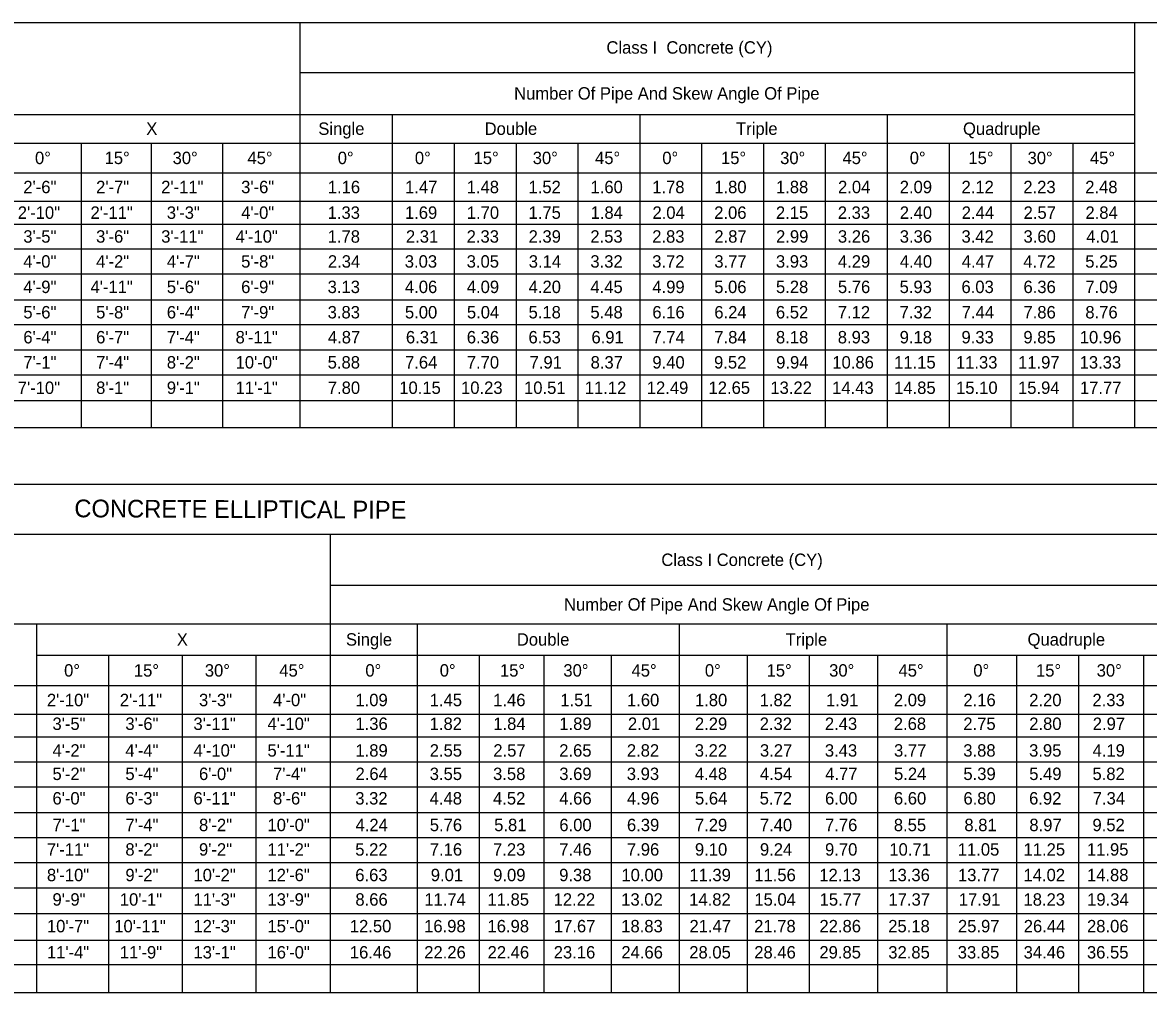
# Model space of a CAD drawing. Extents: x 10029 to 10796, y 10063 to 10519.
# Drawn here: x 10299.4 to 10616.8, y 10063.2 to 10336.7 of the extents above; entities that cross this region are included whole.
import ezdxf

# ---------------------------------------------------------------- set-up
doc = ezdxf.new("R2010")
doc.units = 0
doc.layers.add('Default', color=7, linetype='Continuous')
doc.layers.add('Dimension', color=7, linetype='Continuous')

msp = doc.modelspace()

# ---------------------------------------------------------------- linework, layer by layer
at = {"layer": 'Default'}
for p, q in [((10039.72, 10336.74), (10681.45, 10336.74)), ((10377.67, 10222.58), (10377.67, 10336.74)), ((10612.98, 10222.58), (10612.98, 10336.74)), ((10377.67, 10322.67), (10612.98, 10322.67)), ((10079.67, 10310.85), (10612.98, 10310.85)), ((10403.72, 10222.58), (10403.72, 10310.85)), ((10473.47, 10222.58), (10473.47, 10310.85)), ((10543.23, 10222.58), (10543.23, 10310.85)), ((10294.71, 10302.76), (10612.98, 10302.76)), ((10315.99, 10222.58), (10315.99, 10302.76)), ((10335.73, 10222.58), (10335.73, 10302.76)), ((10355.84, 10222.58), (10355.84, 10302.76)), ((10421.16, 10222.58), (10421.16, 10302.76)), ((10438.6, 10222.58), (10438.6, 10302.76)), ((10456.04, 10222.58), (10456.04, 10302.76)), ((10490.91, 10222.58), (10490.91, 10302.76)), ((10508.35, 10222.58), (10508.35, 10302.76)), ((10525.79, 10222.58), (10525.79, 10302.76)), ((10560.67, 10222.58), (10560.67, 10302.76)), ((10578.1, 10222.58), (10578.1, 10302.76)), ((10595.54, 10222.58), (10595.54, 10302.76)), ((10039.72, 10294.39), (10681.45, 10294.39)), ((10039.72, 10286.34), (10681.45, 10286.34)), ((10039.72, 10279.92), (10681.45, 10279.92)), ((10039.72, 10272.9), (10681.45, 10272.9)), ((10039.72, 10265.84), (10681.45, 10265.84)), ((10039.72, 10258.56), (10681.45, 10258.56)), ((10039.72, 10251.55), (10681.45, 10251.55)), ((10039.72, 10244.47), (10681.45, 10244.47)), ((10039.72, 10237.36), (10681.45, 10237.36)), ((10039.72, 10230.15), (10681.45, 10230.15)), ((10039.72, 10222.58), (10681.45, 10222.58)), ((10040.76, 10206.56), (10696.75, 10206.56)), ((10040.76, 10192.44), (10696.75, 10192.44)), ((10386.23, 10063.22), (10386.23, 10192.44)), ((10386.23, 10178.05), (10632.55, 10178.05)), ((10084.96, 10167.22), (10632.55, 10167.22)), ((10303.39, 10063.22), (10303.39, 10167.22)), ((10410.73, 10063.22), (10410.73, 10167.22)), ((10484.61, 10063.22), (10484.61, 10167.22)), ((10560.04, 10063.22), (10560.04, 10167.22)), ((10303.39, 10158.32), (10632.55, 10158.32)), ((10323.73, 10063.22), (10323.73, 10158.32)), ((10344.5, 10063.22), (10344.5, 10158.32)), ((10365.25, 10063.22), (10365.25, 10158.32)), ((10428.17, 10063.22), (10428.17, 10158.32)), ((10446.47, 10063.22), (10446.47, 10158.32)), ((10465.46, 10063.22), (10465.46, 10158.32)), ((10503.77, 10063.22), (10503.77, 10158.32)), ((10521.21, 10063.22), (10521.21, 10158.32)), ((10540.54, 10063.22), (10540.54, 10158.32)), ((10579.72, 10063.22), (10579.72, 10158.32)), ((10597.16, 10063.22), (10597.16, 10158.32)), ((10615.46, 10063.22), (10615.46, 10158.32)), ((10040.76, 10149.78), (10696.75, 10149.78)), ((10040.76, 10141.72), (10696.75, 10141.72)), ((10040.76, 10135.31), (10696.75, 10135.31)), ((10040.76, 10128.29), (10696.75, 10128.29)), ((10040.76, 10121.22), (10696.75, 10121.22)), ((10040.76, 10113.95), (10696.75, 10113.95)), ((10040.76, 10106.93), (10696.75, 10106.93)), ((10040.76, 10099.86), (10696.75, 10099.86)), ((10040.76, 10092.75), (10696.75, 10092.75)), ((10040.76, 10085.54), (10696.75, 10085.54)), ((10040.76, 10077.97), (10696.75, 10077.97)), ((10040.76, 10071.08), (10696.75, 10071.08)), ((10040.76, 10063.22), (10696.75, 10063.22))]:
    msp.add_line(p, q, dxfattribs=at)

# ---------------------------------------------------------------- texts
at = {"layer": 'Dimension'}
for s, p in [('Class I  Concrete (CY)', (10463.98, 10327.96)), ('Number Of Pipe And Skew Angle Of Pipe', (10437.96, 10315.01)), ('X', (10334.25, 10305.06)), ('Single', (10382.76, 10305.06)), ('Double', (10429.64, 10305.06)), ('Triple', (10500.53, 10305.06)), ('Quadruple', (10564.51, 10305.06)), ('0°', (10302.89, 10296.82)), ('15°', (10322.51, 10296.82)), ('30°', (10341.68, 10296.82)), ('45°', (10362.78, 10296.82)), ('0°', (10388.24, 10296.82)), ('0°', (10409.98, 10296.82)), ('15°', (10426.53, 10296.82)), ('30°', (10443.21, 10296.82)), ('45°', (10460.78, 10296.82)), ('0°', (10479.74, 10296.82)), ('15°', (10496.28, 10296.82)), ('30°', (10512.96, 10296.82)), ('45°', (10530.53, 10296.82)), ('0°', (10549.49, 10296.82)), ('15°', (10566.03, 10296.82)), ('30°', (10582.71, 10296.82)), ('45°', (10600.29, 10296.82)), ('Class I Concrete (CY)', (10479.46, 10183.49)), ('Number Of Pipe And Skew Angle Of Pipe', (10452.03, 10170.89)), ('X', (10342.87, 10161.02)), ('Single', (10390.55, 10161.02)), ('Double', (10438.72, 10161.02)), ('Triple', (10514.51, 10161.02)), ('Quadruple', (10582.71, 10161.02)), ('0°', (10311.1, 10152.3)), ('15°', (10330.77, 10152.3)), ('30°', (10350.77, 10152.3)), ('45°', (10371.77, 10152.3)), ('0°', (10396.02, 10152.3)), ('0°', (10416.99, 10152.3)), ('15°', (10433.97, 10152.3)), ('30°', (10451.85, 10152.3)), ('45°', (10471.06, 10152.3)), ('0°', (10491.74, 10152.3)), ('15°', (10509.14, 10152.3)), ('30°', (10526.77, 10152.3)), ('45°', (10546.32, 10152.3)), ('0°', (10567.42, 10152.3)), ('15°', (10585.09, 10152.3)), ('30°', (10602.2, 10152.3))]:
    msp.add_text(s, height=3.5, dxfattribs=at).set_placement(p)
for s, height, rotation, p in [('2\'-6"', 3.5, 0, (10299.6, 10288.61)), ('2\'-7"', 3.5, 0, (10320.12, 10288.61)), ('2\'-11"', 3.5, 0, (10338.47, 10288.61)), ('3\'-6"', 3.5, 0, (10361.01, 10288.61)), ('1.16', 3.5, 0, (10385.43, 10288.61)), ('1.47', 3.5, 0, (10407.22, 10288.61)), ('1.48', 3.5, 0, (10424.59, 10288.61)), ('1.52', 3.5, 0, (10442.02, 10288.61)), ('1.60', 3.5, 0, (10459.5, 10288.61)), ('1.78', 3.5, 0, (10476.9, 10288.61)), ('1.80', 3.5, 0, (10494.38, 10288.61)), ('1.88', 3.5, 0, (10511.78, 10288.61)), ('2.04', 3.5, 0, (10529.28, 10288.61)), ('2.09', 3.5, 0, (10546.68, 10288.61)), ('2.12', 3.5, 0, (10564.09, 10288.61)), ('2.23', 3.5, 0, (10581.52, 10288.61)), ('2.48', 3.5, 0, (10598.97, 10288.61)), ('2\'-10"', 3.5, 0, (10298.03, 10281.38)), ('2\'-11"', 3.5, 0, (10318.55, 10281.38)), ('3\'-3"', 3.5, 0, (10340.05, 10281.38)), ('4\'-0"', 3.5, 0, (10361.01, 10281.38)), ('1.33', 3.5, 0, (10385.39, 10281.38)), ('1.69', 3.5, 0, (10407.18, 10281.38)), ('1.70', 3.5, 0, (10424.62, 10281.38)), ('1.75', 3.5, 0, (10442.03, 10281.38)), ('1.84', 3.5, 0, (10459.52, 10281.38)), ('2.04', 3.5, 0, (10476.96, 10281.38)), ('2.06', 3.5, 0, (10494.37, 10281.38)), ('2.15', 3.5, 0, (10511.78, 10281.38)), ('2.33', 3.5, 0, (10529.21, 10281.38)), ('2.40', 3.5, 0, (10546.69, 10281.38)), ('2.44', 3.5, 0, (10564.15, 10281.38)), ('2.57', 3.5, 0, (10581.6, 10281.38)), ('2.84', 3.5, 0, (10599.03, 10281.38)), ('3\'-5"', 3.5, 0, (10299.6, 10274.66)), ('3\'-6"', 3.5, 0, (10320.12, 10274.66)), ('3\'-11"', 3.5, 0, (10338.47, 10274.66)), ('4\'-10"', 3.5, 0, (10359.44, 10274.66)), ('1.78', 3.5, 0, (10385.4, 10274.66)), ('2.31', 3.5, 0, (10407.46, 10274.66)), ('2.33', 3.5, 0, (10424.58, 10274.66)), ('2.39', 3.5, 0, (10442.05, 10274.66)), ('2.53', 3.5, 0, (10459.45, 10274.66)), ('2.83', 3.5, 0, (10476.89, 10274.66)), ('2.87', 3.5, 0, (10494.41, 10274.66)), ('2.99', 3.5, 0, (10511.81, 10274.66)), ('3.26', 3.5, 0, (10529.25, 10274.66)), ('3.36', 3.5, 0, (10546.68, 10274.66)), ('3.42', 3.5, 0, (10564.09, 10274.66)), ('3.60', 3.5, 0, (10581.57, 10274.66)), ('4.01', 3.5, 0, (10599.28, 10274.66)), ('4\'-0"', 3.5, 0, (10299.6, 10267.62)), ('4\'-2"', 3.5, 0, (10320.12, 10267.62)), ('4\'-7"', 3.5, 0, (10340.05, 10267.62)), ('5\'-8"', 3.5, 0, (10361.01, 10267.62)), ('2.34', 3.5, 0, (10385.46, 10267.62)), ('3.03', 3.5, 0, (10407.14, 10267.62)), ('3.05', 3.5, 0, (10424.59, 10267.62)), ('3.14', 3.5, 0, (10442.09, 10267.62)), ('3.32', 3.5, 0, (10459.46, 10267.62)), ('3.72', 3.5, 0, (10476.89, 10267.62)), ('3.77', 3.5, 0, (10494.41, 10267.62)), ('3.93', 3.5, 0, (10511.77, 10267.62)), ('4.29', 3.5, 0, (10529.25, 10267.62)), ('4.40', 3.5, 0, (10546.69, 10267.62)), ('4.47', 3.5, 0, (10564.16, 10267.62)), ('4.72', 3.5, 0, (10581.52, 10267.62)), ('5.25', 3.5, 0, (10598.98, 10267.62)), ('4\'-9"', 3.5, 0, (10299.6, 10260.45)), ('4\'-11"', 3.5, 0, (10318.55, 10260.45)), ('5\'-6"', 3.5, 0, (10340.05, 10260.45)), ('6\'-9"', 3.5, 0, (10361.01, 10260.45)), ('3.13', 3.5, 0, (10385.39, 10260.45)), ('4.06', 3.5, 0, (10407.18, 10260.45)), ('4.09', 3.5, 0, (10424.62, 10260.45)), ('4.20', 3.5, 0, (10442.06, 10260.45)), ('4.45', 3.5, 0, (10459.47, 10260.45)), ('4.99', 3.5, 0, (10476.93, 10260.45)), ('5.06', 3.5, 0, (10494.37, 10260.45)), ('5.28', 3.5, 0, (10511.78, 10260.45)), ('5.76', 3.5, 0, (10529.25, 10260.45)), ('5.93', 3.5, 0, (10546.64, 10260.45)), ('6.03', 3.5, 0, (10564.08, 10260.45)), ('6.36', 3.5, 0, (10581.56, 10260.45)), ('7.09', 3.5, 0, (10599, 10260.45)), ('5\'-6"', 3.5, 0, (10299.6, 10253.3)), ('5\'-8"', 3.5, 0, (10320.12, 10253.3)), ('6\'-4"', 3.5, 0, (10340.05, 10253.3)), ('7\'-9"', 3.5, 0, (10361.01, 10253.3)), ('3.83', 3.5, 0, (10385.39, 10253.3)), ('5.00', 3.5, 0, (10407.18, 10253.3)), ('5.04', 3.5, 0, (10424.65, 10253.3)), ('5.18', 3.5, 0, (10442.03, 10253.3)), ('5.48', 3.5, 0, (10459.47, 10253.3)), ('6.16', 3.5, 0, (10476.93, 10253.3)), ('6.24', 3.5, 0, (10494.4, 10253.3)), ('6.52', 3.5, 0, (10511.77, 10253.3)), ('7.12', 3.5, 0, (10529.21, 10253.3)), ('7.32', 3.5, 0, (10546.65, 10253.3)), ('7.44', 3.5, 0, (10564.15, 10253.3)), ('7.86', 3.5, 0, (10581.56, 10253.3)), ('8.76', 3.5, 0, (10599, 10253.3)), ('6\'-4"', 3.5, 0, (10299.6, 10246.26)), ('6\'-7"', 3.5, 0, (10320.12, 10246.26)), ('8\'-11"', 3.5, 0, (10359.44, 10246.26)), ('4.87', 3.5, 0, (10385.47, 10246.26)), ('6.31', 3.5, 0, (10407.46, 10246.26)), ('6.36', 3.5, 0, (10424.62, 10246.26)), ('6.53', 3.5, 0, (10442.01, 10246.26)), ('6.91', 3.5, 0, (10459.77, 10246.26)), ('7.84', 3.5, 0, (10494.4, 10246.26)), ('8.18', 3.5, 0, (10511.78, 10246.26)), ('8.93', 3.5, 0, (10529.21, 10246.26)), ('9.18', 3.5, 0, (10546.66, 10246.26)), ('9.33', 3.5, 0, (10564.08, 10246.26)), ('9.85', 3.5, 0, (10581.54, 10246.26)), ('10.96', 3.5, 0, (10597.43, 10246.26)), ('7\'-4"', 3.5, 0, (10340.05, 10246.26)), ('7.74', 3.5, 0, (10476.96, 10246.26)), ('7\'-1"', 3.5, 0, (10299.6, 10239.17)), ('7\'-4"', 3.5, 0, (10320.12, 10239.17)), ('8\'-2"', 3.5, 0, (10340.05, 10239.17)), ('10\'-0"', 3.5, 0, (10359.44, 10239.17)), ('5.88', 3.5, 0, (10385.4, 10239.17)), ('7.64', 3.5, 0, (10407.21, 10239.17)), ('7.70', 3.5, 0, (10424.62, 10239.17)), ('7.91', 3.5, 0, (10442.33, 10239.17)), ('8.37', 3.5, 0, (10459.53, 10239.17)), ('9.40', 3.5, 0, (10476.94, 10239.17)), ('9.52', 3.5, 0, (10494.33, 10239.17)), ('9.94', 3.5, 0, (10511.84, 10239.17)), ('10.86', 3.5, 0, (10527.67, 10239.17)), ('11.15', 3.5, 0, (10545.09, 10239.17)), ('11.33', 3.5, 0, (10562.51, 10239.17)), ('11.97', 3.5, 0, (10580.03, 10239.17)), ('13.33', 3.5, 0, (10597.39, 10239.17)), ('7\'-10"', 3.5, 0, (10298.03, 10232.01)), ('8\'-1"', 3.5, 0, (10320.12, 10232.01)), ('9\'-1"', 3.5, 0, (10340.05, 10232.01)), ('11\'-1"', 3.5, 0, (10359.44, 10232.01)), ('7.80', 3.5, 0, (10385.44, 10232.01)), ('10.15', 3.5, 0, (10405.58, 10232.01)), ('10.23', 3.5, 0, (10423, 10232.01)), ('10.51', 3.5, 0, (10440.76, 10232.01)), ('11.12', 3.5, 0, (10457.88, 10232.01)), ('12.49', 3.5, 0, (10475.36, 10232.01)), ('12.65', 3.5, 0, (10492.77, 10232.01)), ('13.22', 3.5, 0, (10510.2, 10232.01)), ('14.43', 3.5, 0, (10527.63, 10232.01)), ('14.85', 3.5, 0, (10545.09, 10232.01)), ('15.10', 3.5, 0, (10562.56, 10232.01)), ('15.94', 3.5, 0, (10580.02, 10232.01)), ('17.77', 3.5, 0, (10597.47, 10232.01)), ('CONCRETE ELLIPTICAL PIPE', 5, 359.7555, (10313.98, 10197.23)), ('2\'-10"', 3.5, 0, (10306.25, 10143.95)), ('2\'-11"', 3.5, 0, (10326.8, 10143.95)), ('3\'-3"', 3.5, 0, (10349.13, 10143.95)), ('4\'-0"', 3.5, 0, (10370, 10143.95)), ('1.09', 3.5, 0, (10393.22, 10143.95)), ('1.45', 3.5, 0, (10414.17, 10143.95)), ('1.46', 3.5, 0, (10432.06, 10143.95)), ('1.51', 3.5, 0, (10450.98, 10143.95)), ('1.60', 3.5, 0, (10469.78, 10143.95)), ('1.80', 3.5, 0, (10488.94, 10143.95)), ('1.82', 3.5, 0, (10507.19, 10143.95)), ('1.91', 3.5, 0, (10525.89, 10143.95)), ('2.09', 3.5, 0, (10545.03, 10143.95)), ('2.16', 3.5, 0, (10564.62, 10143.95)), ('2.20', 3.5, 0, (10583.18, 10143.95)), ('2.33', 3.5, 0, (10601, 10143.95)), ('3\'-5"', 3.5, 0, (10307.82, 10137.25)), ('3\'-6"', 3.5, 0, (10328.37, 10137.25)), ('3\'-11"', 3.5, 0, (10347.56, 10137.25)), ('4\'-10"', 3.5, 0, (10368.43, 10137.25)), ('1.36', 3.5, 0, (10393.22, 10137.25)), ('1.82', 3.5, 0, (10414.15, 10137.25)), ('1.84', 3.5, 0, (10432.09, 10137.25)), ('1.89', 3.5, 0, (10450.7, 10137.25)), ('2.01', 3.5, 0, (10470.05, 10137.25)), ('2.29', 3.5, 0, (10488.93, 10137.25)), ('2.32', 3.5, 0, (10507.19, 10137.25)), ('2.43', 3.5, 0, (10525.57, 10137.25)), ('2.68', 3.5, 0, (10545, 10137.25)), ('2.75', 3.5, 0, (10564.6, 10137.25)), ('2.80', 3.5, 0, (10583.18, 10137.25)), ('2.97', 3.5, 0, (10601.09, 10137.25)), ('4\'-2"', 3.5, 0, (10307.82, 10129.73)), ('4\'-4"', 3.5, 0, (10328.37, 10129.73)), ('4\'-10"', 3.5, 0, (10347.56, 10129.73)), ('5\'-11"', 3.5, 0, (10368.43, 10129.73)), ('1.89', 3.5, 0, (10393.22, 10129.73)), ('2.55', 3.5, 0, (10414.17, 10129.73)), ('2.57', 3.5, 0, (10432.1, 10129.73)), ('2.65', 3.5, 0, (10450.68, 10129.73)), ('2.82', 3.5, 0, (10469.74, 10129.73)), ('3.22', 3.5, 0, (10488.89, 10129.73)), ('3.27', 3.5, 0, (10507.27, 10129.73)), ('3.43', 3.5, 0, (10525.57, 10129.73)), ('3.77', 3.5, 0, (10545.07, 10129.73)), ('3.88', 3.5, 0, (10564.59, 10129.73)), ('3.95', 3.5, 0, (10583.15, 10129.73)), ('4.19', 3.5, 0, (10601.04, 10129.73)), ('5\'-2"', 3.5, 0, (10307.82, 10123.13)), ('5\'-4"', 3.5, 0, (10328.37, 10123.13)), ('6\'-0"', 3.5, 0, (10349.13, 10123.13)), ('7\'-4"', 3.5, 0, (10370, 10123.13)), ('2.64', 3.5, 0, (10393.25, 10123.13)), ('3.55', 3.5, 0, (10414.17, 10123.13)), ('3.58', 3.5, 0, (10432.03, 10123.13)), ('3.69', 3.5, 0, (10450.7, 10123.13)), ('3.93', 3.5, 0, (10469.73, 10123.13)), ('4.48', 3.5, 0, (10488.9, 10123.13)), ('4.54', 3.5, 0, (10507.26, 10123.13)), ('4.77', 3.5, 0, (10525.66, 10123.13)), ('5.24', 3.5, 0, (10545.06, 10123.13)), ('5.39', 3.5, 0, (10564.62, 10123.13)), ('5.49', 3.5, 0, (10583.18, 10123.13)), ('5.82', 3.5, 0, (10601.01, 10123.13)), ('6\'-0"', 3.5, 0, (10307.82, 10116.23)), ('6\'-3"', 3.5, 0, (10328.37, 10116.23)), ('6\'-11"', 3.5, 0, (10347.56, 10116.23)), ('8\'-6"', 3.5, 0, (10370, 10116.23)), ('3.32', 3.5, 0, (10393.18, 10116.23)), ('4.48', 3.5, 0, (10414.16, 10116.23)), ('4.52', 3.5, 0, (10432.02, 10116.23)), ('4.66', 3.5, 0, (10450.7, 10116.23)), ('4.96', 3.5, 0, (10469.77, 10116.23)), ('5.64', 3.5, 0, (10488.96, 10116.23)), ('5.72', 3.5, 0, (10507.19, 10116.23)), ('6.00', 3.5, 0, (10525.62, 10116.23)), ('6.60', 3.5, 0, (10545.04, 10116.23)), ('6.80', 3.5, 0, (10564.63, 10116.23)), ('6.92', 3.5, 0, (10583.14, 10116.23)), ('7.34', 3.5, 0, (10601.08, 10116.23)), ('7\'-1"', 3.5, 0, (10307.82, 10108.71)), ('7\'-4"', 3.5, 0, (10328.37, 10108.71)), ('8\'-2"', 3.5, 0, (10349.13, 10108.71)), ('10\'-0"', 3.5, 0, (10368.43, 10108.71)), ('4.24', 3.5, 0, (10393.25, 10108.71)), ('5.76', 3.5, 0, (10414.19, 10108.71)), ('5.81', 3.5, 0, (10432.34, 10108.71)), ('6.00', 3.5, 0, (10450.71, 10108.71)), ('6.39', 3.5, 0, (10469.77, 10108.71)), ('7.29', 3.5, 0, (10488.93, 10108.71)), ('7.40', 3.5, 0, (10507.24, 10108.71)), ('7.76', 3.5, 0, (10525.61, 10108.71)), ('8.55', 3.5, 0, (10545.01, 10108.71)), ('8.81', 3.5, 0, (10564.9, 10108.71)), ('8.97', 3.5, 0, (10583.22, 10108.71)), ('9.52', 3.5, 0, (10601.01, 10108.71)), ('7\'-11"', 3.5, 0, (10306.25, 10101.81)), ('8\'-2"', 3.5, 0, (10328.37, 10101.81)), ('9\'-2"', 3.5, 0, (10349.13, 10101.81)), ('11\'-2"', 3.5, 0, (10368.43, 10101.81)), ('5.22', 3.5, 0, (10393.18, 10101.81)), ('7.16', 3.5, 0, (10414.19, 10101.81)), ('7.23', 3.5, 0, (10432.02, 10101.81)), ('7.46', 3.5, 0, (10450.7, 10101.81)), ('7.96', 3.5, 0, (10469.77, 10101.81)), ('9.10', 3.5, 0, (10488.94, 10101.81)), ('9.24', 3.5, 0, (10507.26, 10101.81)), ('9.70', 3.5, 0, (10525.62, 10101.81)), ('10.71', 3.5, 0, (10543.74, 10101.81)), ('11.05', 3.5, 0, (10563.03, 10101.81)), ('11.25', 3.5, 0, (10581.58, 10101.81)), ('11.95', 3.5, 0, (10599.45, 10101.81)), ('8\'-10"', 3.5, 0, (10306.25, 10094.6)), ('9\'-2"', 3.5, 0, (10328.37, 10094.6)), ('10\'-2"', 3.5, 0, (10347.56, 10094.6)), ('12\'-6"', 3.5, 0, (10368.43, 10094.6)), ('6.63', 3.5, 0, (10393.18, 10094.6)), ('9.01', 3.5, 0, (10414.47, 10094.6)), ('9.09', 3.5, 0, (10432.06, 10094.6)), ('9.38', 3.5, 0, (10450.67, 10094.6)), ('10.00', 3.5, 0, (10468.21, 10094.6)), ('11.39', 3.5, 0, (10487.36, 10094.6)), ('11.56', 3.5, 0, (10505.66, 10094.6)), ('12.13', 3.5, 0, (10524, 10094.6)), ('13.36', 3.5, 0, (10543.46, 10094.6)), ('13.77', 3.5, 0, (10563.09, 10094.6)), ('14.02', 3.5, 0, (10581.57, 10094.6)), ('14.88', 3.5, 0, (10599.45, 10094.6)), ('9\'-9"', 3.5, 0, (10307.82, 10087.7)), ('10\'-1"', 3.5, 0, (10326.8, 10087.7)), ('11\'-3"', 3.5, 0, (10347.56, 10087.7)), ('13\'-9"', 3.5, 0, (10368.43, 10087.7)), ('8.66', 3.5, 0, (10393.22, 10087.7)), ('11.74', 3.5, 0, (10412.65, 10087.7)), ('11.85', 3.5, 0, (10430.46, 10087.7)), ('12.22', 3.5, 0, (10449.09, 10087.7)), ('13.02', 3.5, 0, (10468.16, 10087.7)), ('14.82', 3.5, 0, (10487.32, 10087.7)), ('15.04', 3.5, 0, (10505.69, 10087.7)), ('15.77', 3.5, 0, (10524.09, 10087.7)), ('17.37', 3.5, 0, (10543.5, 10087.7)), ('17.91', 3.5, 0, (10563.33, 10087.7)), ('18.23', 3.5, 0, (10581.57, 10087.7)), ('19.34', 3.5, 0, (10599.51, 10087.7)), ('10\'-7"', 3.5, 0, (10306.25, 10080.18)), ('10\'-11"', 3.5, 0, (10325.23, 10080.18)), ('12\'-3"', 3.5, 0, (10347.56, 10080.18)), ('15\'-0"', 3.5, 0, (10368.43, 10080.18)), ('12.50', 3.5, 0, (10391.65, 10080.18)), ('16.98', 3.5, 0, (10412.59, 10080.18)), ('16.98', 3.5, 0, (10430.46, 10080.18)), ('17.67', 3.5, 0, (10449.17, 10080.18)), ('18.83', 3.5, 0, (10468.16, 10080.18)), ('21.47', 3.5, 0, (10487.4, 10080.18)), ('21.78', 3.5, 0, (10505.63, 10080.18)), ('22.86', 3.5, 0, (10524.04, 10080.18)), ('25.18', 3.5, 0, (10543.43, 10080.18)), ('25.97', 3.5, 0, (10563.09, 10080.18)), ('26.44', 3.5, 0, (10581.64, 10080.18)), ('28.06', 3.5, 0, (10599.47, 10080.18)), ('11\'-4"', 3.5, 0, (10306.25, 10072.81)), ('11\'-9"', 3.5, 0, (10326.8, 10072.81)), ('13\'-1"', 3.5, 0, (10347.56, 10072.81)), ('16\'-0"', 3.5, 0, (10368.43, 10072.81)), ('16.46', 3.5, 0, (10391.65, 10072.81)), ('22.26', 3.5, 0, (10412.62, 10072.81)), ('22.46', 3.5, 0, (10430.49, 10072.81)), ('23.16', 3.5, 0, (10449.13, 10072.81)), ('24.66', 3.5, 0, (10468.2, 10072.81)), ('28.05', 3.5, 0, (10487.34, 10072.81)), ('28.46', 3.5, 0, (10505.66, 10072.81)), ('29.85', 3.5, 0, (10524.02, 10072.81)), ('32.85', 3.5, 0, (10543.44, 10072.81)), ('33.85', 3.5, 0, (10563.03, 10072.81)), ('34.46', 3.5, 0, (10581.6, 10072.81)), ('36.55', 3.5, 0, (10599.45, 10072.81))]:
    msp.add_text(s, height=height, rotation=rotation, dxfattribs=at).set_placement(p)

doc.saveas('drawing.dxf')
